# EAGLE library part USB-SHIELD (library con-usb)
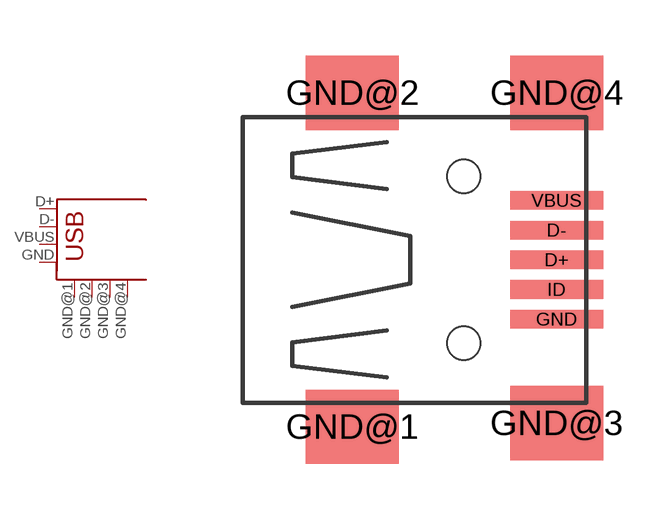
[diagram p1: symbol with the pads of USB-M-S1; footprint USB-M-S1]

Designator prefix -

## USB-SHIELD  [USB-M-S1]
D+  D+
D-  D-
GND  GND
GND@1  GND
GND@2  GND
GND@3  GND
GND@4  GND
VBUS  VBUS

## Footprint USB-M-S1 (pad centres in mm)
smd 2.5 x 0.5: D+ 2.75,0; D- 2.75,0.8; GND 2.75,-1.6; ID 2.75,-0.8; VBUS 2.75,1.6
smd 2.5 x 2: GND@1 -2.75,-4.5; GND@2 -2.75,4.5; GND@3 2.75,-4.4; GND@4 2.75,4.5
hole 0.9 at 0.25,2.25
hole 0.9 at 0.25,-2.25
